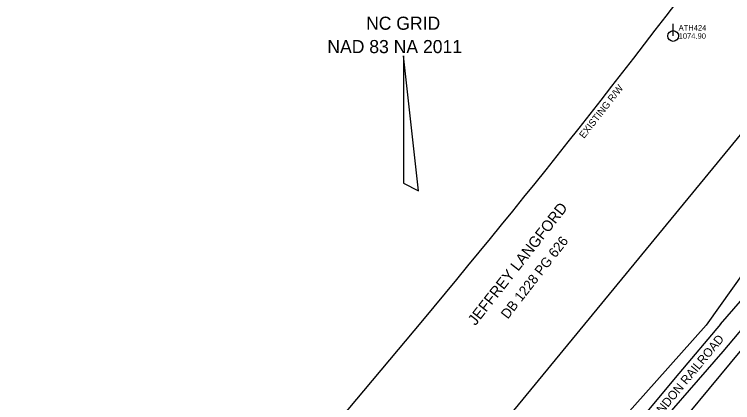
# Model space of a CAD drawing. Extents: x 1116345 to 1117546, y 660629 to 661859.
# Drawn here: x 1116641.8 to 1116970, y 661402.8 to 661580.4 of the extents above; entities that cross this region are included whole.
import ezdxf

# ---------------------------------------------------------------- set-up
doc = ezdxf.new("R2010")
doc.units = 0
for name, color, linetype in [('CTL North Arrow NAD 83 NA 2011 CELL', 7, 'Continuous'), ('Exist Property Deed Book Text', 7, 'Continuous'), ('Exist Property Owner Text', 7, 'Continuous'), ('Exist Right of Way Line', 7, 'Continuous'), ('Exist Right of Way Line Text', 7, 'Continuous'), ('Exist Roads Soil', 7, 'Continuous'), ('Exist Roads Soil Text', 7, 'Continuous'), ('Exist Utilities Power Pole CELL', 7, 'Continuous'), ('Exist Utilities Power Pole Cogo Elevation', 7, 'Continuous'), ('Exist Utilities Power Pole Cogo Number', 7, 'Continuous'), ('Exist Vegetation Woods Line', 7, 'Continuous')]:
    doc.layers.add(name, color=color, linetype=linetype)

msp = doc.modelspace()

# ---------------------------------------------------------------- linework, layer by layer
at = {"layer": 'CTL North Arrow NAD 83 NA 2011 CELL'}
msp.add_lwpolyline([(1116819.6, 661503.14), (1116826.47, 661499.72), (1116819.6, 661561.46)], close=True, dxfattribs=at)
at = {"layer": 'Exist Right of Way Line'}
for p, q in [((1116687.81, 661177.38), (1116997.4, 661554.39)), ((1116641.8, 661217.47), (1116828.39, 661440.36))]:
    msp.add_line(p, q, dxfattribs=at)
msp.add_arc((1113861.12, 663924.32), 3869.72, 320.06667, 327.74218, dxfattribs=at)
at = {"layer": 'Exist Roads Soil'}
for points in [[(1116964.44, 661438.72), (1116986.86, 661464.48), (1117002.48, 661483.48), (1117033.75, 661528.36), (1117059.44, 661564.38), (1117076.95, 661588.51), (1117096.75, 661617.23), (1117115.73, 661643.92), (1117143.77, 661689), (1117184.56, 661750.96), (1117213.34, 661797.09), (1117219.45, 661808.47)], [(1116964.44, 661438.72), (1116945.52, 661416.08), (1116900.3, 661361.98), (1116874.25, 661330.53), (1116855.61, 661308.4), (1116830.71, 661278.94), (1116793.69, 661231.48), (1116772.98, 661208.42), (1116757.77, 661186.14), (1116728.04, 661149.83), (1116727.06, 661148.51)], [(1116733.8, 661143.62), (1116741.64, 661154.44), (1116759.33, 661176.15), (1116773.88, 661197.09), (1116797.54, 661224.23), (1116813.71, 661245.14), (1116851.6, 661289.9), (1116871.06, 661313.76), (1116898.57, 661347.77), (1116927.81, 661382.57), (1116965.68, 661426.24), (1116975.46, 661437.79)]]:
    msp.add_lwpolyline(points, dxfattribs=at)
at = {"layer": 'Exist Utilities Power Pole CELL'}
for q in [(1116942.87, 661576.14), (1116942.87, 661570.51)]:
    msp.add_line((1116942.87, 661570.51), q, dxfattribs=at)
msp.add_circle((1116942.87, 661570.51), 2.45, dxfattribs=at)
at = {"layer": 'Exist Vegetation Woods Line'}
for points in [[(1117208.66, 661815.33), (1117061.61, 661584.19), (1116958.01, 661438.28)], [(1116740.57, 661137.11), (1116758.17, 661158.85), (1116797.8, 661207.69), (1116868.5, 661301.41), (1116920.29, 661361.98), (1116989.01, 661444.95)], [(1116958.01, 661438.28), (1116907.79, 661381.94), (1116862.4, 661323.56), (1116809.86, 661263.44), (1116743.73, 661176.53), (1116723.64, 661152.6)]]:
    msp.add_lwpolyline(points, dxfattribs=at)

# ---------------------------------------------------------------- texts
at = {"layer": 'CTL North Arrow NAD 83 NA 2011 CELL'}
for s, p in [('NC GRID', (1116802.52, 661573.35)), ('NAD 83 NA 2011', (1116784.83, 661562.67))]:
    msp.add_text(s, height=6, dxfattribs=at).set_placement(p)
at = {"layer": 'Exist Property Deed Book Text'}
msp.add_text('DB 1228 PG 626', height=4.5, rotation=52.1366, dxfattribs=at).set_placement((1116867.29, 661440.74))
at = {"layer": 'Exist Property Owner Text'}
msp.add_text('JEFFREY LANGFORD', height=5, rotation=51.9041, dxfattribs=at).set_placement((1116852.52, 661437.75))
at = {"layer": 'Exist Right of Way Line Text'}
msp.add_text('EXISTING R/W', height=3.2, rotation=51.9435, dxfattribs=at).set_placement((1116902.12, 661523.4))
at = {"layer": 'Exist Roads Soil Text'}
msp.add_text('ABANDON RAILROAD  ', height=4, rotation=50.3709, dxfattribs=at).set_placement((1116931.13, 661389.21))
at = {"layer": 'Exist Utilities Power Pole Cogo Elevation'}
msp.add_text('1074.90', height=2.5, dxfattribs=at).set_placement((1116945.37, 661569.26))
at = {"layer": 'Exist Utilities Power Pole Cogo Number'}
msp.add_text('ATH424', height=2.5, dxfattribs=at).set_placement((1116945.37, 661573.01))

doc.saveas('drawing.dxf')
